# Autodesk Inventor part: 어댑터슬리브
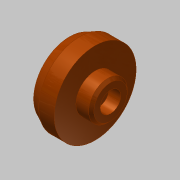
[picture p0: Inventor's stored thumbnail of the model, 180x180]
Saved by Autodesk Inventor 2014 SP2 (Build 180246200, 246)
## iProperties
Created: 2016-06
Part Number: 어댑터슬리브
Material: 강철, 탄소
Document SubType Name: Modeling
Designer: mduedu
Density: 7.87 g/cm^3
Appearance: 매끄러움 - 연한 주황색
Author: mduedu
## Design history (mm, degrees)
sketch "스케치2"
  geometry: L1 (0, 0)-(0, 14); L2 (0, 14)-(-4, 16); L3 (-4, 16)-(-10, 16); L4 (-10, 16)-(-10, 7.5); L5 (-10, 7.5)-(-16, 7.5); L6 (-16, 7.5)-(-16, 0); L7 (-16, 0)-(0, 0)
  constraints: 14 end point, 4 parallel, 1 perpendicular, 1 vertical
  dimensions: "d0" = 32 diameter of L3 L7; "d2" = 28 diameter of L1.end L7; "d3" = 6 distance of L2.end L3.end; "d4" = 6 distance of L4.end L5.end; "d5" = 15 diameter of L5 L7; "d6" = 16 distance between parallel lines of L6 L1
revolve "회전1" sketch "스케치2" stored, may be unused: angle "d7" = 90 deg
sketch "스케치3"
  geometry: L1 (-16, -7.5)-(-16, 7.5) reference; L2 (-16, 7.5)-(-10, 7.5) reference; L3 (-10, 7.5)-(-10, 16) reference; L4 (-10, 16)-(-4, 16) reference; L5 (-4, 16)-(0, 14) reference; L6 (0, 14)-(0, -14) reference; L7 (0, -14)-(-4, -16) reference; L8 (-4, -16)-(-10, -16) reference; L9 (-10, -16)-(-10, -7.5) reference; L10 (-10, -7.5)-(-16, -7.5) reference; L11 (0, 10)-(-5, 10); L12 (-5, 10)-(-5, 8); L13 (-5, 8)-(-7, 6); L14 (-7, 6)-(-7, 0); L15 (-7, 0)-(0, 0); L16 (0, 10)-(0, 0)
  constraints: 12 end point, 3 parallel, 2 perpendicular, 1 point on line
  dimensions: "d8" = 20 diameter of L11 L15; "d10" = 16 diameter of L12.end L15; "d11" = 12 diameter of L13.end L15; "d12" = 9 distance between parallel lines of L14 L1; "d13" = 2 distance between parallel lines of L12 L14
revolve "회전2" sketch "스케치3" stored, may be unused: angle "d14" = 90 deg
chamfer "모따기1" distance "d15" = 1; stored, may be unused: second distance "d16" = 2, angle "d17" = 45 deg
sketch "스케치4"
  geometry: 2 further points
  constraints: 1 coincident
sketch "스케치5"
  geometry: 1 further point
hole "구멍1" sketch "스케치5" at (0, 0) diameter "d18" = 4.5; stored, may be unused: countersink angle "d22" = 90 deg, drill point angle "d24" = 0 deg; dims "d19" = 6, "d20" = 8, "d21" = 4.6, "d23" = 8
node "솔리드1"
node "절단 모서리 투영1"
